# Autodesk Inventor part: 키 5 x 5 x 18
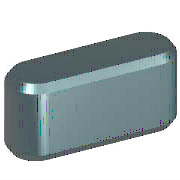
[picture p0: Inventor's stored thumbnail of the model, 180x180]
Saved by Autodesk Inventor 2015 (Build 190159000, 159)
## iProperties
IsCustomPart: 1
Created: 2012-02
Part Number: 키 5 x 5 x 18
Material: 강철, 연강
Description: 키 및 해당 키홈
Document SubType Name: Modeling
Standard: KS B 1311
Designer: mduedu
Standards Organization: KS
Language: ko-KR
Size Designation: 5 x 5 x 18
Categories: <MemberInstance><Categories><Category DisplayName="샤프트 부품" InternalName="7f7aeb1f-a693-4053-b835-cee3144e0d98" Mnemonic="SHFT"><Category DisplayName="키" Interna
Density: 1 g/cm^3
Appearance: 금색
Author: mduedu
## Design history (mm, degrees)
workplane "Work Plane1"
workplane "Work Plane2"
sketch "스케치1"
  geometry: L1 (2.5, 2.5)-(15.5, 2.5); L2 (15.5, -2.5)-(2.5, -2.5); L3 (0, 9.4)-(0, -7.4) reference; L4 (-5, 0)-(30, 0) reference; L5 (18, 0)-(18, 7); A1 r 2.5 centre (2.5, 0) between (2.5, 2.5) and (2.5, -2.5); A2 r 2.5 centre (15.5, 0) between (15.5, -2.5) and (15.5, 2.5)
  constraints: 6 end point, 5 point on circle, 4 tangent, 3 point on line, 2 centre point, 1 horizontal, 1 parallel, 1 perpendicular
  dimensions: "d0" = 2.5 radius of A1 (= 0.5 x PB); "d13" = 2.5 radius of A2 (= 0.5 x PB); "d14" = 18 distance between parallel lines of L5 L3 (= NLG)
extrude "본체1" new body sketch "스케치1" taper "d3" = 0 deg; stored distance "d4" = 10
workplane "Work Plane3"
body "Solid1"
chamfer "모따기1" distance "d8" = 0.4 (= PHH); stored, may be unused: second distance "d9" = 0.4 (= PHH), angle "d15" = 45 deg
other parameters: "d1" = -3 (= -PNT), "d2" = 2 (= PH - PNT), "NLG" = 18 [user parameter; used in 3 equation terms], "PB" = 5 [user parameter; used in 2 equation terms], "PNT" = 3 [user parameter; used in 2 equation terms], "PH" = 5 [user parameter; used in 1 equation term], "PHH" = 0.4 [user parameter; used in 2 equation terms], "d10" = 0, "d16" = 0, "d17" = 0, "d18" = 0, "WDMIN" = 12 [user parameter], "PLB2" = 18 (= NLG) [user parameter], "WDMAX" = 17 [user parameter], "PLB1" = 18 (= NLG) [user parameter], "RR" = 0.16 [user parameter], "PUEB" = 2.3 [user parameter]
